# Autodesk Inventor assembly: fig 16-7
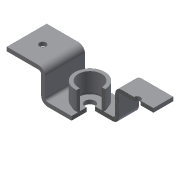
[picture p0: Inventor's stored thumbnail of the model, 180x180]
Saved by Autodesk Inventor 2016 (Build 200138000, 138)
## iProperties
Created: 2005-03
Part Number: fig 16-7
Document SubType Name: Weldment
Designer: CADCIM
Manufacturer: Standard
Standards Organization: Custom
Author: CADCIM
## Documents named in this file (3)
- D:\KAVITA\Autodesk Inventor_ 2016 Project_Kavita\Inventor_Part Files\Inventor_2016_Part\c16_Inv_2016\c16_inv_2016_prt\fig 16-7\fig 16-7.iam
- D:\KAVITA\Autodesk Inventor_ 2016 Project_Kavita\Inventor_Part Files\Inventor_2016_Part\c16_Inv_2016\c16_inv_2016_prt\fig 16-7\Bracket.ipt
- D:\KAVITA\Autodesk Inventor_ 2016 Project_Kavita\Inventor_Part Files\Inventor_2016_Part\c16_Inv_2016\c16_inv_2016_prt\fig 16-7\cylinder.ipt
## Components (2 placed, 2 different names)
1. Bracket:1 — Insert:1
2. cylinder:1 — Insert:1
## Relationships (1: Insert 1)
- Insert:1: Bracket:1 ↔ cylinder:1
